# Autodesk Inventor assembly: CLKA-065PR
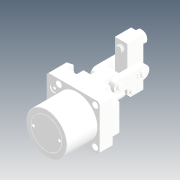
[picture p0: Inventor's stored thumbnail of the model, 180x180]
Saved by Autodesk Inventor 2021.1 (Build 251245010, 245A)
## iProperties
Created: 2018-10
Part Number: CLKA-065PR
Description: STEP AP214
Document SubType Name: Assembly
Designer: user
Title: CLKA-065PR.STEP
Revision Number: ÈÎºÎ
Sending System: SolidWorks 2016
Preprocessor: SwSTEP 2.0
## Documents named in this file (11)
- D:\Vault_2016\Projekty\Clamptek\Hydraulic\CLKA-P\Inventor\CLKA-065PR\CLKA-065PR.iam
- D:\Vault_2016\Projekty\Clamptek\Hydraulic\CLKA-P\Inventor\CLKA-065PR\CLKA-065P-R.ipt
- D:\Vault_2016\Projekty\Clamptek\Hydraulic\CLKA-P\Inventor\CLKA-065PR\dadangjuan.ipt
- D:\Vault_2016\Projekty\Clamptek\Hydraulic\CLKA-P\Inventor\CLKA-065PR\duanxiao.ipt
- D:\Vault_2016\Projekty\Clamptek\Hydraulic\CLKA-P\Inventor\CLKA-065PR\liangan.ipt
- D:\Vault_2016\Projekty\Clamptek\Hydraulic\CLKA-P\Inventor\CLKA-065PR\luomu.ipt
- D:\Vault_2016\Projekty\Clamptek\Hydraulic\CLKA-P\Inventor\CLKA-065PR\luosi.ipt
- D:\Vault_2016\Projekty\Clamptek\Hydraulic\CLKA-P\Inventor\CLKA-065PR\yabi.ipt
- D:\Vault_2016\Projekty\Clamptek\Hydraulic\CLKA-P\Inventor\CLKA-065PR\zhangxiao.ipt
- D:\Vault_2016\Projekty\Clamptek\Hydraulic\CLKA-P\Inventor\CLKA-065PR\8MMdangjuan.ipt
- D:\Vault_2016\Projekty\Clamptek\Hydraulic\CLKA-P\Inventor\CLKA-065PR\¶ÂÍ·G4-1.ipt
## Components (17 placed, 17 different names)
1. CLKA-065P-R_1
2. dadangjuan_2
3. duanxiao_3
4. liangan_4
5. luomu_5
6. luosi_6
7. yabi_7
8. zhangxiao_8
9. 8MMdangjuan_9
10. liangan_10
11. zhangxiao_11
12. dadangjuan_12
13. dadangjuan_13
14. dadangjuan_14
15. 8MMdangjuan_15
16. ¶ÂÍ·G4-1_16
17. ¶ÂÍ·G4-1_17
